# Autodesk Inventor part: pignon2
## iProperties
Author: Administrateur
Shininess: 20.0
PropertySet Name: _Private Model Information
Length Units: 11269
Angle Units: 11283
Time Units: 11279
Mass Units: 11290
Length Display Precision: 3
Angle Display Precision: 2
Compacted: False
Created: 2001-04
Part Number: pignon2
Material: Par défaut
Document SubType Name: Modélisation
Designer: Administrateur
Control State: 0
Master: False
Checked Out: False
PropertySet Name: Design Tracking Control
Density: 0.0
Volumn: 0.0
Area: 0.0
PropertySet Name: Model Information
